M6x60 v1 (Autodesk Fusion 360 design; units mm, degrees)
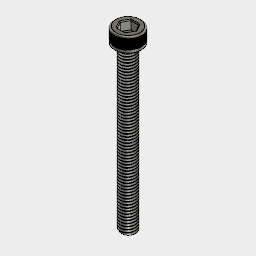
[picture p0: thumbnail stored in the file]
sketch "スケッチ1"
  circle C1 centre (0, 0) radius 3
  circle C2 centre (0, 0) radius 5
  dimension "d1" diameter C1 = 6
  dimension "d2" diameter C2 = 10
extrude "押し出し1" new body sketch "スケッチ1" blind 5.8
sketch "スケッチ2" plane through (0, 0, 5.8) normal (0, 0, 1) x axis (-1, 0, 0)
  line L1 (-1.4722, -2.55) -> (-2.9445, 0)
  line L2 (1.4722, -2.55) -> (-1.4722, -2.55)
  line L3 (2.9445, 0) -> (1.4722, -2.55)
  line L4 (1.4722, 2.55) -> (2.9445, 0)
  line L5 (-1.4722, 2.55) -> (1.4722, 2.55)
  line L6 (-2.9445, 0) -> (-1.4722, 2.55)
  circle C1 centre (0, 0) radius 5
  dimension "d5" distance L2 L5 = 5.1
work_plane "作業平面" sketch "スケッチ2" AlongDistance -0.75
extrude "押し出し2" cut sketch "スケッチ2" profile of L1 L2 L3 L4 L5 L6 against normal blind 3.3
chamfer "面取り" distance 0.3
sketch "スケッチ3" plane through (0, 0, 5.05) normal (0, 0, 1) x axis (1, 0, 0)
  line L1 (-0.05, 4.9497) -> (-0.05, 4.9997)
  line L2 (0.05, 4.9497) -> (-0.05, 4.9497)
  line L3 (0.05, 4.9997) -> (0.05, 4.9497)
  circle C1 centre (0, 0) radius 5
  point P4 (-0.05, 4.9497)
  point P5 (0.05, 4.9497)
  point P3 (-0.05, 4.9997)
  point P6 (0.05, 4.9997)
  dimension "d18" distance P4 P5 = 0.1
  dimension "d19" distance P3 P4 = 0.05
  dimension "d20" distance P5 P6 = 0.05 (= "d19")
extrude "押し出し3" cut sketch "スケッチ3" against normal blind 3.6
work_axis "作業軸"
circular_pattern "C パターン" countU 100 TotalAngle 360
fillet "フィレット1" radius 0.6
extrude "押し出し4" add sketch "スケッチ1" profile of C1 blind -60
thread "ねじ"
fillet "フィレット2" sketch "スケッチ3" radius 0.5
